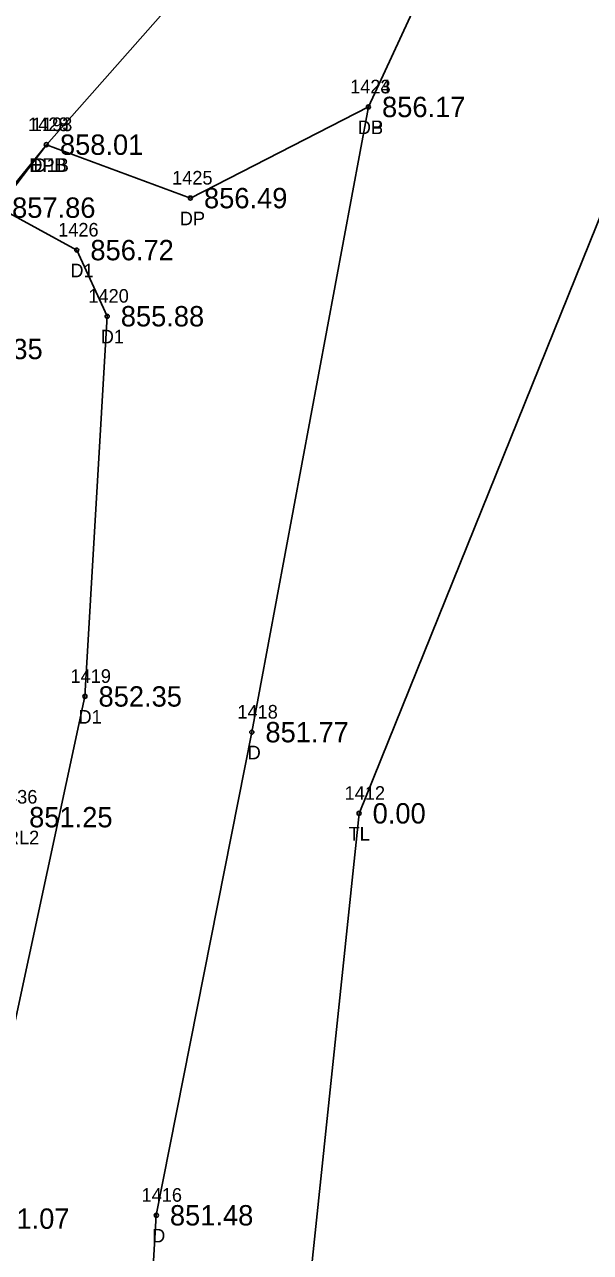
# Model space of a CAD drawing. Extents: x 1448136 to 1453623, y 1125056 to 1128842.
# Drawn here: x 1450760.7 to 1450802.4, y 1126902.1 to 1126992.5 of the extents above; entities that cross this region are included whole.
import ezdxf

# ---------------------------------------------------------------- set-up
doc = ezdxf.new("R2010")
doc.units = 0
for name, color, linetype in [('RD_EX_Driveway', 7, 'Continuous'), ('RD_EX_Driveway_txCode', 7, 'Continuous'), ('RD_EX_H2O_txCode', 7, 'Continuous'), ('RD_EX_Road', 7, 'Continuous'), ('RD_EX_Road_txCode', 7, 'Continuous'), ('RD_EX_TX_Driveway_ELEV', 7, 'Continuous'), ('RD_EX_TX_H2O_ELEV', 7, 'Continuous'), ('RD_EX_TX_Road_ELEV', 7, 'Continuous'), ('RD_EX_TX_UT_ELEV', 7, 'Continuous'), ('RD_EX_TX_VEG_ELEV', 7, 'Continuous'), ('RD_EX_VEG', 7, 'Continuous'), ('RD_EX_VEG_txCode', 7, 'Continuous'), ('RD_SMD_Locator', 7, 'Continuous')]:
    doc.layers.add(name, color=color, linetype=linetype)

msp = doc.modelspace()

# ---------------------------------------------------------------- linework, layer by layer
at = {"layer": 'RD_EX_Driveway'}
for points in [[(1450797.398, 1127023.382), (1450800.445, 1127017.656), (1450786.03, 1126986.463), (1450772.935, 1126979.753), (1450762.34, 1126983.686)], [(1450768.27, 1126867.798), (1450770.428, 1126904.876), (1450777.452, 1126940.441), (1450786.03, 1126986.463)], [(1450755.319, 1126870.088), (1450756.908, 1126904.63), (1450765.178, 1126943.07), (1450766.814, 1126971.057), (1450764.578, 1126975.925), (1450758.819, 1126979.051), (1450762.34, 1126983.686)]]:
    msp.add_lwpolyline(points, dxfattribs=at)
at = {"layer": 'RD_EX_Road'}
msp.add_lwpolyline([(1450889.116, 1127140.054), (1450857.394, 1127100.421), (1450825.548, 1127060.756), (1450804.119, 1127034.173), (1450797.398, 1127023.382), (1450762.34, 1126983.686), (1450751.567, 1126970.399)], dxfattribs=at)
at = {"layer": 'RD_EX_VEG'}
msp.add_lwpolyline([(1451989.542, 1126836.983), (1451893.841, 1126905.641), (1451857.366, 1126942.275), (1451815.217, 1126966.534), (1451772.506, 1126993.524), (1451734.11, 1127020.415), (1451632.197, 1127074.856), (1451559.169, 1127115.621), (1451479.776, 1127184.414), (1451388.573, 1127251.259), (1451326.316, 1127287.157), (1451271.863, 1127300.714), (1451149.567, 1127304.549), (1451077.688, 1127285.442), (1451030.083, 1127262.146), (1450963.079, 1127198.603), (1450901.455, 1127121.236), (1450895.954, 1127120.379), (1450805.012, 1126983.224), (1450785.34, 1126934.464), (1450777.852, 1126863.097)], dxfattribs=at)
at = {"layer": 'RD_SMD_Locator'}
for centre in [(1450786.03, 1126986.463), (1450786.03, 1126986.463), (1450762.34, 1126983.686), (1450762.34, 1126983.686), (1450762.34, 1126983.686), (1450772.935, 1126979.753), (1450764.578, 1126975.925), (1450766.814, 1126971.057), (1450765.178, 1126943.07), (1450777.452, 1126940.441), (1450785.34, 1126934.464), (1450770.428, 1126904.876)]:
    msp.add_circle(centre, 0.15, dxfattribs=at)

# ---------------------------------------------------------------- texts
at = {"layer": 'RD_EX_Driveway_txCode'}
for s, p in [('1423', (1450784.684, 1126987.463)), ('1424', (1450784.684, 1126987.463)), ('1428', (1450760.994, 1126984.686)), ('1429', (1450760.994, 1126984.686)), ('DP', (1450785.251, 1126984.463)), ('DB', (1450785.251, 1126984.463)), ('DPB', (1450761.088, 1126981.686)), ('D1B', (1450761.395, 1126981.686)), ('1425', (1450771.589, 1126980.753)), ('DP', (1450772.155, 1126977.753)), ('1426', (1450763.207, 1126976.925)), ('D1', (1450764.105, 1126973.925)), ('1420', (1450765.428, 1126972.057)), ('D1', (1450766.342, 1126969.057)), ('1419', (1450764.115, 1126944.07)), ('D1', (1450764.705, 1126941.07)), ('1418', (1450776.389, 1126941.441)), ('D', (1450777.145, 1126938.441)), ('1416', (1450769.341, 1126905.876)), ('D', (1450770.121, 1126902.876))]:
    msp.add_text(s, height=1, dxfattribs=at).set_placement(p)
at = {"layer": 'RD_EX_H2O_txCode'}
for s, p in [('1436', (1450758.704, 1126935.183)), ('CRL2', (1450758.397, 1126932.183))]:
    msp.add_text(s, height=1, dxfattribs=at).set_placement(p)
at = {"layer": 'RD_EX_Road_txCode'}
for s, p in [('1193', (1450761.277, 1126984.686)), ('EPL', (1450761.136, 1126981.686))]:
    msp.add_text(s, height=1, dxfattribs=at).set_placement(p)
at = {"layer": 'RD_EX_TX_Driveway_ELEV'}
for s, p in [('856.17', (1450787.03, 1126985.713)), ('856.17', (1450787.03, 1126985.713)), ('858.01', (1450763.34, 1126982.936)), ('858.01', (1450763.34, 1126982.936)), ('856.49', (1450773.935, 1126979.003)), ('857.86', (1450759.819, 1126978.301)), ('856.72', (1450765.578, 1126975.175)), ('855.88', (1450767.814, 1126970.307)), ('852.35', (1450766.178, 1126942.32)), ('851.77', (1450778.452, 1126939.691)), ('851.07', (1450757.908, 1126903.88)), ('851.48', (1450771.428, 1126904.126))]:
    msp.add_text(s, height=1.5, dxfattribs=at).set_placement(p)
at = {"layer": 'RD_EX_TX_H2O_ELEV'}
msp.add_text('851.25', height=1.5, dxfattribs=at).set_placement((1450761.074, 1126933.433))
at = {"layer": 'RD_EX_TX_Road_ELEV'}
msp.add_text('858.01', height=1.5, dxfattribs=at).set_placement((1450763.34, 1126982.936))
at = {"layer": 'RD_EX_TX_UT_ELEV'}
msp.add_text('857.35', height=1.5, dxfattribs=at).set_placement((1450755.936, 1126967.895))
at = {"layer": 'RD_EX_TX_VEG_ELEV'}
msp.add_text('0.00', height=1.5, dxfattribs=at).set_placement((1450786.34, 1126933.714))
at = {"layer": 'RD_EX_VEG_txCode'}
for s, p in [('1412', (1450784.277, 1126935.464)), ('TL', (1450784.568, 1126932.464))]:
    msp.add_text(s, height=1, dxfattribs=at).set_placement(p)

doc.saveas('drawing.dxf')
